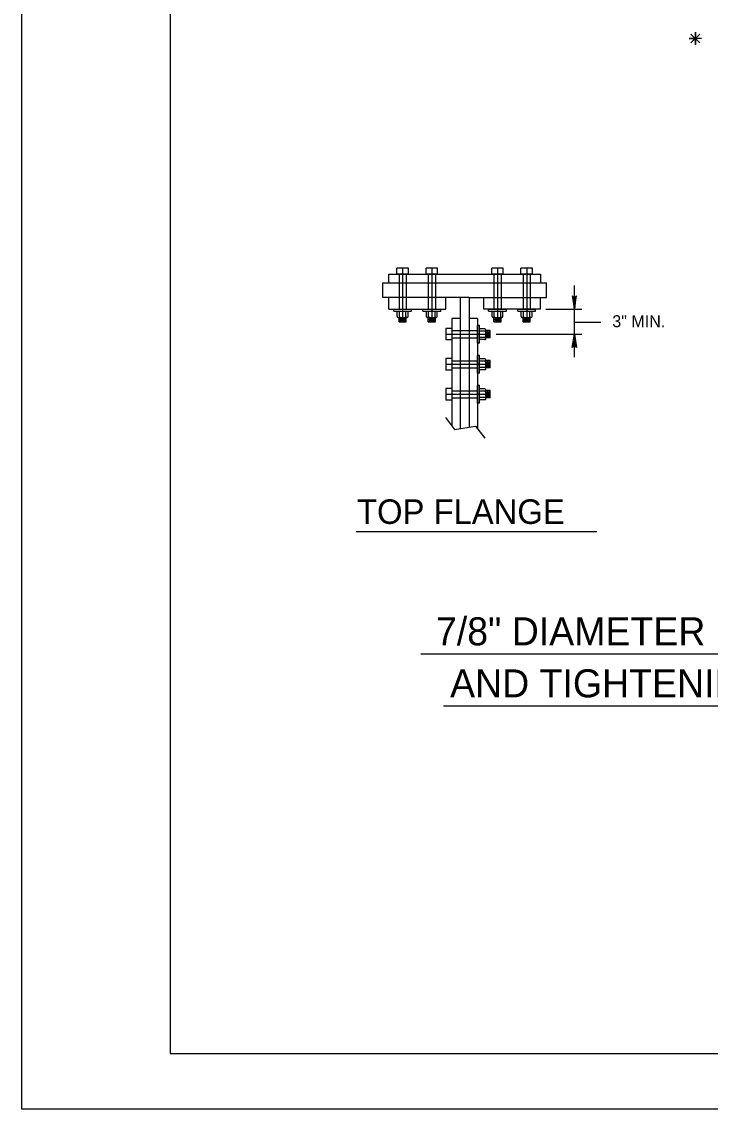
# Model space of a CAD drawing. Extents: x 638466 to 639375, y 297808 to 298996.
# Drawn here: x 638466 to 638651.7, y 297808.5 to 298101.9 of the extents above; entities that cross this region are included whole.
import ezdxf

# ---------------------------------------------------------------- set-up
doc = ezdxf.new("R2010")
doc.units = 0
for name, color, linetype in [('1', 7, 'Continuous'), ('2', 7, 'Continuous'), ('4', 7, 'Continuous'), ('PLT-BNDY', 7, 'Continuous')]:
    doc.layers.add(name, color=color, linetype=linetype)

msp = doc.modelspace()

# ---------------------------------------------------------------- linework, layer by layer
at = {"layer": '1'}
for p, q in [((638505.96, 298387.46), (638505.96, 297823.46)), ((638570.26, 298035.37), (638567.18, 298035.37)), ((638567.18, 298033.76), (638567.18, 298035.37)), ((638570.26, 298033.76), (638567.18, 298033.76)), ((638567.74, 298033.75), (638567.74, 298024.3)), ((638568.72, 298035.37), (638568.72, 298021.13)), ((638569.7, 298033.75), (638569.7, 298024.3)), ((638570.26, 298033.76), (638570.26, 298035.37)), ((638578.14, 298035.37), (638575.05, 298035.37)), ((638575.05, 298033.76), (638575.05, 298035.37)), ((638578.14, 298033.76), (638575.05, 298033.76)), ((638575.62, 298033.75), (638575.62, 298024.3)), ((638576.6, 298035.37), (638576.6, 298021.13)), ((638577.58, 298033.75), (638577.58, 298024.3)), ((638578.14, 298033.76), (638578.14, 298035.37)), ((638595.86, 298035.37), (638592.78, 298035.37)), ((638592.78, 298033.76), (638592.78, 298035.37)), ((638595.86, 298033.76), (638592.78, 298033.76)), ((638593.34, 298033.75), (638593.34, 298024.3)), ((638594.32, 298035.37), (638594.32, 298021.13)), ((638595.3, 298033.75), (638595.3, 298024.3)), ((638595.86, 298033.76), (638595.86, 298035.37)), ((638603.73, 298035.37), (638600.65, 298035.37)), ((638600.65, 298033.76), (638600.65, 298035.37)), ((638603.73, 298033.76), (638600.65, 298033.76)), ((638601.21, 298033.75), (638601.21, 298024.3)), ((638602.2, 298035.37), (638602.2, 298021.13)), ((638603.17, 298033.75), (638603.17, 298024.3)), ((638603.73, 298033.76), (638603.73, 298035.37)), ((638566.33, 298023.77), (638566.33, 298024.31)), ((638566.33, 298024.3), (638571.12, 298024.3)), ((638566.33, 298023.77), (638571.12, 298023.77)), ((638567.27, 298022.36), (638567.27, 298023.77)), ((638567.5, 298022.09), (638569.94, 298022.09)), ((638567.74, 298020.89), (638567.74, 298022.09)), ((638567.86, 298022.36), (638567.86, 298023.77)), ((638569.59, 298022.36), (638569.59, 298023.77)), ((638569.7, 298020.89), (638569.7, 298022.09)), ((638570.17, 298022.36), (638570.17, 298023.77)), ((638571.12, 298023.77), (638571.12, 298024.31)), ((638574.2, 298023.77), (638574.2, 298024.31)), ((638574.2, 298024.3), (638578.99, 298024.3)), ((638574.2, 298023.77), (638578.99, 298023.77)), ((638575.14, 298022.36), (638575.14, 298023.77)), ((638575.38, 298022.09), (638577.81, 298022.09)), ((638575.61, 298020.89), (638575.61, 298022.09)), ((638575.73, 298022.36), (638575.73, 298023.77)), ((638577.46, 298022.36), (638577.46, 298023.77)), ((638577.58, 298020.89), (638577.58, 298022.09)), ((638578.05, 298022.36), (638578.05, 298023.77)), ((638578.99, 298023.77), (638578.99, 298024.31)), ((638591.92, 298023.77), (638591.92, 298024.31)), ((638591.92, 298024.3), (638596.71, 298024.3)), ((638591.92, 298023.77), (638596.71, 298023.77)), ((638592.86, 298022.36), (638592.86, 298023.77)), ((638593.1, 298022.09), (638595.53, 298022.09)), ((638593.34, 298020.89), (638593.34, 298022.09)), ((638593.45, 298022.36), (638593.45, 298023.77)), ((638595.18, 298022.36), (638595.18, 298023.77)), ((638595.3, 298020.89), (638595.3, 298022.09)), ((638595.77, 298022.36), (638595.77, 298023.77)), ((638596.71, 298023.77), (638596.71, 298024.31)), ((638599.8, 298023.77), (638599.8, 298024.31)), ((638599.8, 298024.3), (638604.59, 298024.3)), ((638599.8, 298023.77), (638604.59, 298023.77)), ((638600.74, 298022.36), (638600.74, 298023.77)), ((638600.98, 298022.09), (638603.41, 298022.09)), ((638601.21, 298020.89), (638601.21, 298022.09)), ((638601.33, 298022.36), (638601.33, 298023.77)), ((638603.06, 298022.36), (638603.06, 298023.77)), ((638603.17, 298020.89), (638603.17, 298022.09)), ((638603.65, 298022.36), (638603.65, 298023.77)), ((638604.59, 298023.77), (638604.59, 298024.31)), ((638567.74, 298021.55), (638569.7, 298021.55)), ((638567.74, 298021.01), (638569.7, 298021.01)), ((638567.74, 298020.89), (638569.7, 298020.89)), ((638567.98, 298021.82), (638569.47, 298021.82)), ((638567.98, 298021.28), (638569.47, 298021.28)), ((638575.61, 298021.55), (638577.58, 298021.55)), ((638575.61, 298021.01), (638577.58, 298021.01)), ((638575.61, 298020.89), (638577.58, 298020.89)), ((638575.85, 298021.82), (638577.34, 298021.82)), ((638575.85, 298021.28), (638577.34, 298021.28)), ((638580.36, 298019.09), (638580.36, 298016.01)), ((638581.98, 298019.09), (638580.36, 298019.09)), ((638581.98, 298019.09), (638581.98, 298016.01)), ((638589.47, 298019.95), (638588.93, 298019.95)), ((638588.94, 298015.16), (638588.94, 298019.95)), ((638589.47, 298015.16), (638589.47, 298019.95)), ((638590.88, 298019.01), (638589.47, 298019.01)), ((638593.34, 298021.55), (638595.3, 298021.55)), ((638593.34, 298021.01), (638595.3, 298021.01)), ((638593.34, 298020.89), (638595.3, 298020.89)), ((638593.57, 298021.82), (638595.06, 298021.82)), ((638593.57, 298021.28), (638595.06, 298021.28)), ((638601.21, 298021.55), (638603.17, 298021.55)), ((638601.21, 298021.01), (638603.17, 298021.01)), ((638601.21, 298020.89), (638603.17, 298020.89)), ((638601.45, 298021.82), (638602.94, 298021.82)), ((638601.45, 298021.28), (638602.94, 298021.28)), ((638580.37, 298017.55), (638592.11, 298017.55)), ((638581.98, 298018.53), (638588.94, 298018.53)), ((638581.98, 298016.57), (638588.94, 298016.57)), ((638590.88, 298018.42), (638589.47, 298018.42)), ((638590.88, 298016.69), (638589.47, 298016.69)), ((638590.88, 298016.1), (638589.47, 298016.1)), ((638591.15, 298016.34), (638591.15, 298018.77)), ((638592.35, 298018.54), (638591.15, 298018.54)), ((638592.35, 298016.57), (638591.15, 298016.57)), ((638591.42, 298016.81), (638591.42, 298018.3)), ((638591.69, 298016.57), (638591.69, 298018.54)), ((638591.96, 298016.81), (638591.96, 298018.3)), ((638592.23, 298016.57), (638592.23, 298018.54)), ((638592.35, 298016.57), (638592.35, 298018.54)), ((638581.98, 298016.01), (638580.36, 298016.01)), ((638589.47, 298015.16), (638588.93, 298015.16)), ((638580.36, 298010.99), (638580.36, 298007.91)), ((638581.98, 298010.99), (638580.36, 298010.99)), ((638581.98, 298010.99), (638581.98, 298007.91)), ((638581.98, 298010.43), (638588.94, 298010.43)), ((638589.47, 298011.85), (638588.93, 298011.85)), ((638588.94, 298007.06), (638588.94, 298011.85)), ((638589.47, 298007.06), (638589.47, 298011.85)), ((638590.88, 298010.91), (638589.47, 298010.91)), ((638590.88, 298010.32), (638589.47, 298010.32)), ((638591.15, 298008.24), (638591.15, 298010.67)), ((638592.35, 298010.44), (638591.15, 298010.44)), ((638591.42, 298008.71), (638591.42, 298010.2)), ((638591.69, 298008.47), (638591.69, 298010.44)), ((638591.96, 298008.71), (638591.96, 298010.2)), ((638592.23, 298008.47), (638592.23, 298010.44)), ((638592.35, 298008.47), (638592.35, 298010.44)), ((638581.98, 298007.91), (638580.36, 298007.91)), ((638580.37, 298009.45), (638592.11, 298009.45)), ((638581.98, 298008.47), (638588.94, 298008.47)), ((638590.88, 298008.59), (638589.47, 298008.59)), ((638590.88, 298008), (638589.47, 298008)), ((638592.35, 298008.47), (638591.15, 298008.47)), ((638589.47, 298007.06), (638588.93, 298007.06)), ((638580.36, 298002.89), (638580.36, 297999.81)), ((638581.98, 298002.89), (638580.36, 298002.89)), ((638581.98, 298002.89), (638581.98, 297999.81)), ((638581.98, 298002.33), (638588.94, 298002.33)), ((638589.47, 298003.75), (638588.93, 298003.75)), ((638588.94, 297998.96), (638588.94, 298003.75)), ((638589.47, 297998.96), (638589.47, 298003.75)), ((638590.88, 298002.81), (638589.47, 298002.81)), ((638590.88, 298002.22), (638589.47, 298002.22)), ((638591.15, 298000.14), (638591.15, 298002.57)), ((638592.35, 298002.34), (638591.15, 298002.34)), ((638591.42, 298000.61), (638591.42, 298002.1)), ((638591.69, 298000.37), (638591.69, 298002.34)), ((638591.96, 298000.61), (638591.96, 298002.1)), ((638592.23, 298000.37), (638592.23, 298002.34)), ((638592.35, 298000.37), (638592.35, 298002.34)), ((638581.98, 297999.81), (638580.36, 297999.81)), ((638580.37, 298001.35), (638592.11, 298001.35)), ((638581.98, 298000.37), (638588.94, 298000.37)), ((638589.47, 297998.96), (638588.93, 297998.96)), ((638590.88, 298000.49), (638589.47, 298000.49)), ((638590.88, 297999.9), (638589.47, 297999.9)), ((638592.35, 298000.37), (638591.15, 298000.37)), ((638505.96, 297823.46), (639291.96, 297823.46))]:
    msp.add_line(p, q, dxfattribs=at)
for points in [[(638614.62, 298027.74), (638614.87, 298027.61), (638615.05, 298024.3), (638614.62, 298027.74), (638614.47, 298027.91), (638615.05, 298024.3), (638615.22, 298027.61), (638615.46, 298027.72), (638615.05, 298024.3), (638615.63, 298027.91), (638615.46, 298027.72)], [(638614.62, 298014.12), (638614.87, 298014.25), (638615.05, 298017.55), (638614.62, 298014.12), (638614.47, 298013.94), (638615.05, 298017.55), (638615.22, 298014.25), (638615.46, 298014.13), (638615.05, 298017.55), (638615.63, 298013.94), (638615.46, 298014.13)]]:
    msp.add_lwpolyline(points, dxfattribs=at)
for centre, major_axis, start_param, end_param in [((638567.5, 298022.36), (0, 0.269), 1.570796, 3.141593), ((638567.62, 298022.36), (0, -0.269), 0, 1.570796), ((638568.09, 298022.36), (0, 0.269), 1.570796, 3.141593), ((638569.35, 298022.36), (0, -0.269), 0, 1.570796), ((638569.82, 298022.36), (0, 0.269), 1.570796, 3.141593), ((638569.94, 298022.36), (0, -0.269), 0, 1.570796), ((638575.38, 298022.36), (0, 0.269), 1.570796, 3.141593), ((638575.5, 298022.36), (0, -0.269), 0, 1.570796), ((638575.97, 298022.36), (0, 0.269), 1.570796, 3.141593), ((638577.22, 298022.36), (0, -0.269), 0, 1.570796), ((638577.7, 298022.36), (0, 0.269), 1.570796, 3.141593), ((638577.81, 298022.36), (0, -0.269), 0, 1.570796), ((638593.1, 298022.36), (0, 0.269), 1.570796, 3.141593), ((638593.22, 298022.36), (0, -0.269), 0, 1.570796), ((638593.69, 298022.36), (0, 0.269), 1.570796, 3.141593), ((638594.95, 298022.36), (0, -0.269), 0, 1.570796), ((638595.42, 298022.36), (0, 0.269), 1.570796, 3.141593), ((638595.53, 298022.36), (0, -0.269), 0, 1.570796), ((638600.98, 298022.36), (0, 0.269), 1.570796, 3.141593), ((638601.09, 298022.36), (0, -0.269), 0, 1.570796), ((638601.56, 298022.36), (0, 0.269), 1.570796, 3.141593), ((638602.82, 298022.36), (0, -0.269), 0, 1.570796), ((638603.29, 298022.36), (0, 0.269), 1.570796, 3.141593), ((638603.41, 298022.36), (0, -0.269), 0, 1.570796), ((638590.88, 298018.77), (0.269, 0), 0, 1.570796), ((638590.88, 298018.65), (-0.269, 0), 1.570796, 3.141593), ((638590.88, 298018.18), (0.269, 0), 0, 1.570796), ((638590.88, 298016.93), (-0.269, 0), 1.570796, 3.141593), ((638590.88, 298016.45), (0.269, 0), 0, 1.570796), ((638590.88, 298016.34), (-0.269, 0), 1.570796, 3.141593), ((638590.88, 298010.67), (0.269, 0), 0, 1.570796), ((638590.88, 298010.55), (-0.269, 0), 1.570796, 3.141593), ((638590.88, 298010.08), (0.269, 0), 0, 1.570796), ((638590.88, 298008.83), (-0.269, 0), 1.570796, 3.141593), ((638590.88, 298008.35), (0.269, 0), 0, 1.570796), ((638590.88, 298008.24), (-0.269, 0), 1.570796, 3.141593), ((638590.88, 298002.57), (0.269, 0), 0, 1.570796), ((638590.88, 298002.45), (-0.269, 0), 1.570796, 3.141593), ((638590.88, 298001.98), (0.269, 0), 0, 1.570796), ((638590.88, 298000.73), (-0.269, 0), 1.570796, 3.141593), ((638590.88, 298000.25), (0.269, 0), 0, 1.570796), ((638590.88, 298000.14), (-0.269, 0), 1.570796, 3.141593)]:
    msp.add_ellipse(centre, major_axis=major_axis, ratio=0.875, start_param=start_param, end_param=end_param, dxfattribs=at)
at = {"layer": '2'}
for p, q in [((638564.98, 298033.75), (638605.94, 298033.75)), ((638564.98, 298031.39), (638564.98, 298033.75)), ((638605.94, 298033.75), (638605.94, 298031.39)), ((638563.41, 298031.39), (638607.51, 298031.39)), ((638563.41, 298027.45), (638563.41, 298031.39)), ((638607.51, 298027.45), (638607.51, 298031.39)), ((638586.64, 298027.45), (638563.41, 298027.45)), ((638564.98, 298024.3), (638564.98, 298027.45)), ((638580.34, 298024.3), (638580.34, 298027.45)), ((638584.28, 298027.45), (638584.28, 297992.1)), ((638586.64, 298027.45), (638586.64, 297992.47)), ((638586.64, 298027.45), (638607.51, 298027.45)), ((638590.58, 298024.3), (638590.58, 298027.45)), ((638605.94, 298024.3), (638605.94, 298027.45)), ((638564.98, 298024.3), (638580.34, 298024.3)), ((638605.94, 298024.3), (638590.58, 298024.3)), ((638581.98, 298021.85), (638581.98, 297992.85)), ((638584.28, 298021.85), (638581.98, 298021.85)), ((638588.93, 298021.85), (638586.64, 298021.85)), ((638588.94, 298021.85), (638588.94, 297992.07)), ((638580.29, 297995.06), (638582.75, 297991.86)), ((638582.75, 297991.86), (638588.42, 297992.74)), ((638588.42, 297992.74), (638590.88, 297989.54))]:
    msp.add_line(p, q, dxfattribs=at)
at = {"layer": '4'}
for p, q in [((638647.69, 298097.37), (638647.69, 298097.37)), ((638615.05, 298011.37), (638615.06, 298030.71)), ((638607.38, 298024.3), (638617.06, 298024.3)), ((638615.05, 298020.8), (638622.21, 298020.8)), ((638593.98, 298017.55), (638617.06, 298017.55)), ((638621.1, 297964.25), (638556.14, 297964.25)), ((638776.33, 297931.2), (638573.64, 297931.2)), ((638768.09, 297917.23), (638579.72, 297917.23))]:
    msp.add_line(p, q, dxfattribs=at)
msp.add_lwpolyline([(638649.37, 298097.37), (638646, 298097.37), (638647.69, 298097.37), (638647.69, 298095.68), (638647.69, 298099.06), (638647.69, 298097.37), (638648.88, 298098.56), (638646.49, 298096.18), (638647.69, 298097.37), (638648.88, 298096.18), (638646.49, 298098.56)], dxfattribs=at)
at = {"layer": 'PLT-BNDY'}
msp.add_lwpolyline([(638465.96, 298402.46), (639306.96, 298402.46), (639306.96, 297808.46), (638465.96, 297808.46)], close=True, dxfattribs=at)

# ---------------------------------------------------------------- texts
at = {"layer": '4'}
for s, height, p in [('3" MIN.', 3.24, (638625.28, 298019.45)), ('TOP FLANGE', 6.615, (638556.41, 297966.39)), ('7/8" DIAMETER BOLT ENTERING', 7.56, (638577.71, 297933.63)), ('AND TIGHTENING CLEARANCES', 7.56, (638581.52, 297919.59))]:
    msp.add_text(s, height=height, dxfattribs=at).set_placement(p)

doc.saveas('drawing.dxf')
